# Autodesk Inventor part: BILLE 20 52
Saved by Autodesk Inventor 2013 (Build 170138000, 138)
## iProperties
Created: 2012-12
Part Number: BILLE 20 52
Material: Générique
Document SubType Name: Modeling
Designer: jost thierry
Density: 1 g/cm^3
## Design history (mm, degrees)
node "BILLE 20 521"
node "BILLE 20 52"
node "Base1"
